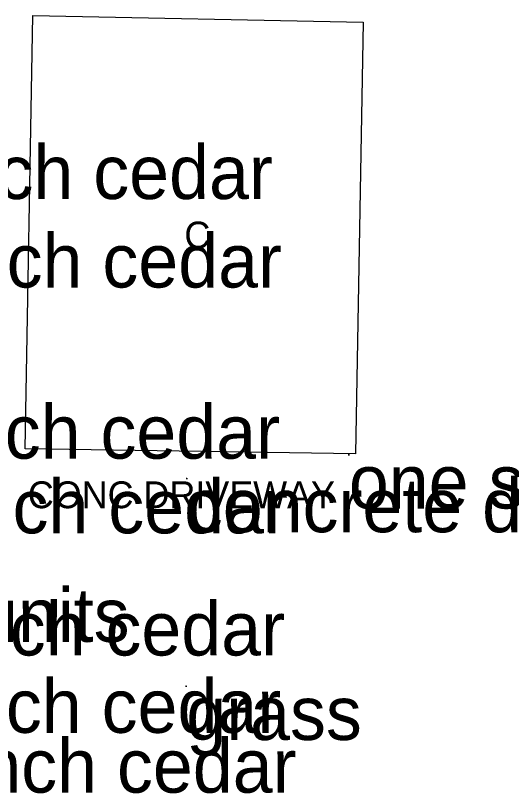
# Model space of a CAD drawing. Extents: x 1802180 to 1804859, y 572524 to 575172.
# Drawn here: x 1803821.5 to 1803867.7, y 573953.5 to 574025.9 of the extents above; entities that cross this region are included whole.
import ezdxf

# ---------------------------------------------------------------- set-up
doc = ezdxf.new("R2010")
doc.units = 0
for name, color, linetype in [('S_BUILDING', 7, 'Continuous'), ('S_BUILDING_ANNOT', 7, 'Continuous'), ('S_DRIVEWAY_ANNOT', 7, 'Continuous'), ('S_MSC_PT_SYM', 7, 'Continuous'), ('S_SURVEY_TEXT_ANNOT', 7, 'Continuous'), ('S_TREE_ANNOT', 7, 'Continuous')]:
    doc.layers.add(name, color=color, linetype=linetype)

msp = doc.modelspace()

# ---------------------------------------------------------------- linework, layer by layer
at = {"layer": 'S_BUILDING'}
msp.add_lwpolyline([(1803853.849, 574025.264), (1803853.136, 573985.075), (1803822.359, 573985.537), (1803823.071, 574025.866), (1803853.849, 574025.264)], dxfattribs=at)
at = {"layer": 'S_MSC_PT_SYM'}
for points in [[(1803852.521, 573984.981), (1803852.521, 573985.031), (1803852.521, 573984.981), (1803852.471, 573984.981), (1803852.521, 573984.981), (1803852.521, 573984.931), (1803852.521, 573984.981), (1803852.571, 573984.981)], [(1803837.432, 573982.77), (1803837.432, 573982.82), (1803837.432, 573982.77), (1803837.382, 573982.77), (1803837.432, 573982.77), (1803837.432, 573982.72), (1803837.432, 573982.77), (1803837.482, 573982.77)], [(1803837.379, 573963.434), (1803837.379, 573963.484), (1803837.379, 573963.434), (1803837.329, 573963.434), (1803837.379, 573963.434), (1803837.379, 573963.384), (1803837.379, 573963.434), (1803837.429, 573963.434)]]:
    msp.add_lwpolyline(points, dxfattribs=at)

# ---------------------------------------------------------------- texts
at = {"layer": 'S_BUILDING_ANNOT'}
msp.add_text('C', height=2.5, dxfattribs=at).set_placement((1803837.199, 574004.186))
at = {"layer": 'S_DRIVEWAY_ANNOT'}
msp.add_text('CONC DRIVEWAY', height=2.5, dxfattribs=at).set_placement((1803822.622, 573980.008))
at = {"layer": 'S_SURVEY_TEXT_ANNOT'}
for s, p in [('one story metal shop', (1803852.521, 573979.981)), ('concrete drive', (1803837.432, 573977.77)), ('one story metal storage units', (1803746.247, 573967.563)), ('grass', (1803837.379, 573958.434))]:
    msp.add_text(s, height=5, dxfattribs=at).set_placement(p)
at = {"layer": 'S_TREE_ANNOT'}
for s, p in [('twin 6 inch cedar', (1803795.267, 574008.787)), ('twin 6 inch cedar', (1803796.119, 574000.551)), ('twin 4 inch cedar', (1803795.94, 573984.618)), ('twin 4 inch cedar', (1803796.67, 573977.67)), ('twin 4 inch cedar', (1803796.406, 573966.299)), ('twin 4 inch cedar', (1803796.051, 573959.099)), ('twin 4 inch cedar', (1803797.477, 573953.529))]:
    msp.add_text(s, height=5, dxfattribs=at).set_placement(p)

doc.saveas('drawing.dxf')
